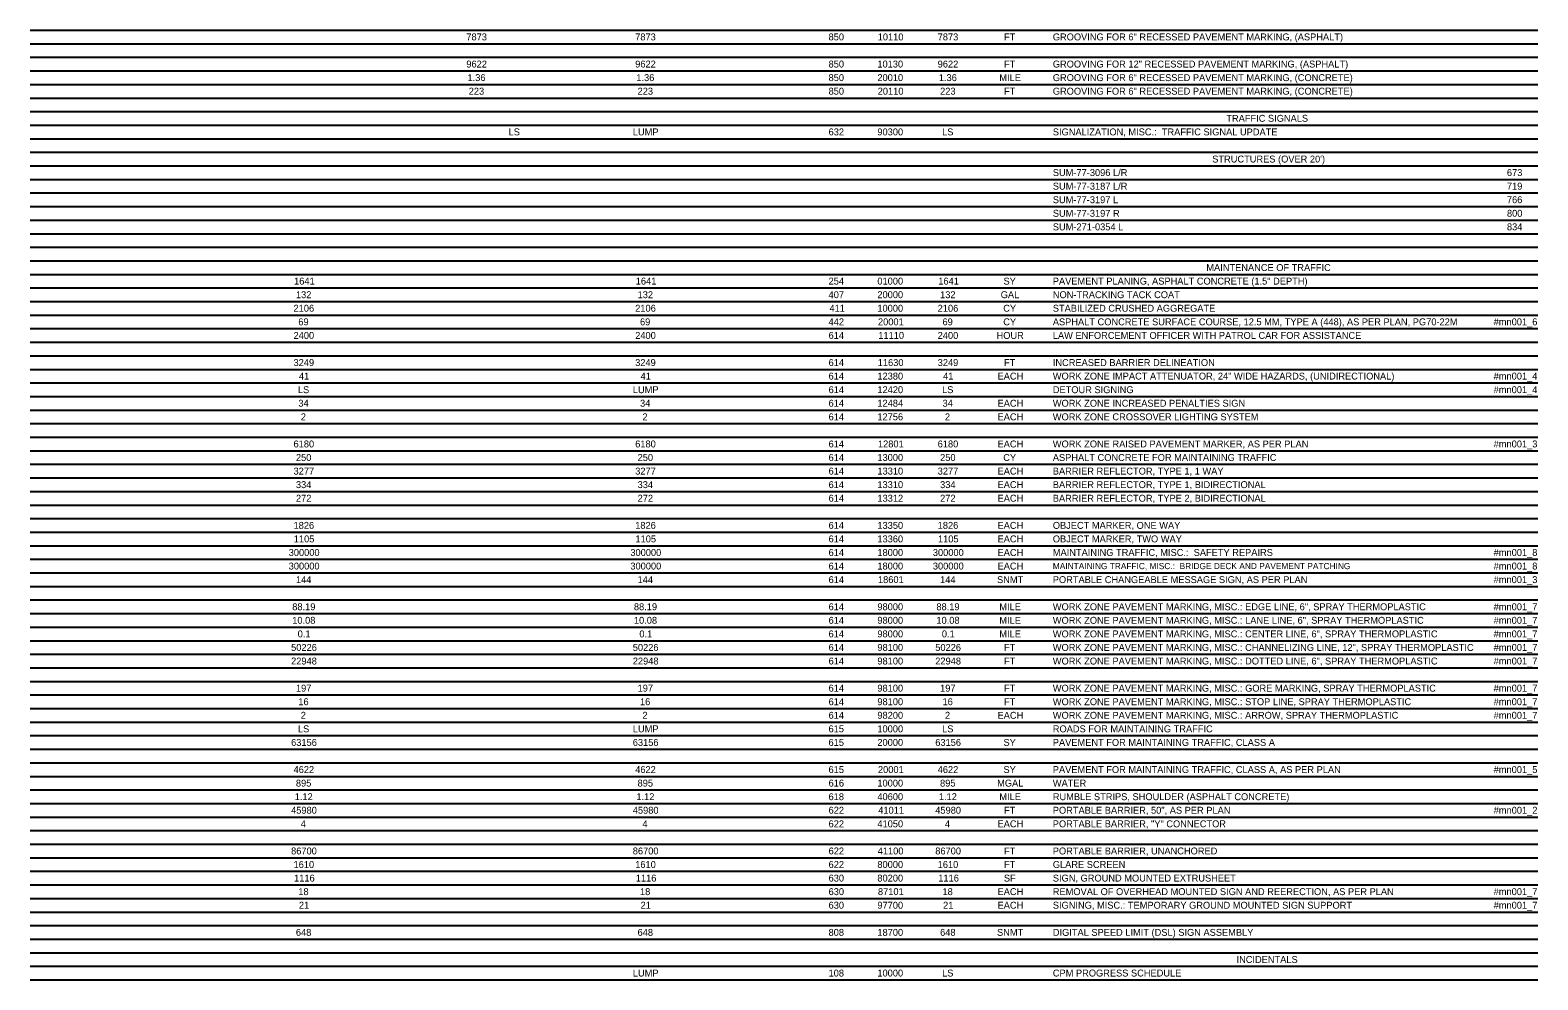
# Model space of a CAD drawing. Extents: x -542 to 295, y -281 to 32.
# Drawn here: x -364.38 to -333.88, y -153.25 to -134.04 of the extents above; entities that cross this region are included whole.
import ezdxf

# ---------------------------------------------------------------- set-up
doc = ezdxf.new("R2010")
doc.units = 0
doc.layers.add('SH_Data', color=7, linetype='Continuous')
doc.layers.add('SH_Text', color=7, linetype='Continuous')

msp = doc.modelspace()

# ---------------------------------------------------------------- linework, layer by layer
at = {"layer": 'SH_Data'}
for p, q in [((-364.38, -134.035), (-333.88, -134.035)), ((-364.38, -134.31), (-333.88, -134.31)), ((-364.38, -134.584), (-333.88, -134.584)), ((-364.38, -134.859), (-333.88, -134.859)), ((-364.38, -135.133), (-333.88, -135.133)), ((-364.38, -135.408), (-333.88, -135.408)), ((-364.38, -135.682), (-333.88, -135.682)), ((-364.38, -135.957), (-333.88, -135.957)), ((-364.38, -136.231), (-333.88, -136.231)), ((-364.38, -136.506), (-333.88, -136.506)), ((-364.38, -136.78), (-333.88, -136.78)), ((-364.38, -137.055), (-333.88, -137.055)), ((-364.38, -137.329), (-333.88, -137.329)), ((-364.38, -137.604), (-333.88, -137.604)), ((-364.38, -137.878), (-333.88, -137.878)), ((-364.38, -138.153), (-333.88, -138.153)), ((-364.38, -138.427), (-333.88, -138.427)), ((-364.38, -138.702), (-333.88, -138.702)), ((-364.38, -138.976), (-333.88, -138.976)), ((-364.38, -139.251), (-333.88, -139.251)), ((-364.38, -139.525), (-333.88, -139.525)), ((-364.38, -139.8), (-333.88, -139.8)), ((-364.38, -140.074), (-333.88, -140.074)), ((-364.38, -140.349), (-333.88, -140.349)), ((-364.38, -140.623), (-333.88, -140.623)), ((-364.38, -140.898), (-333.88, -140.898)), ((-364.38, -141.172), (-333.88, -141.172)), ((-364.38, -141.447), (-333.88, -141.447)), ((-364.38, -141.721), (-333.88, -141.721)), ((-364.38, -141.996), (-333.88, -141.996)), ((-364.38, -142.27), (-333.88, -142.27)), ((-364.38, -142.545), (-333.88, -142.545)), ((-364.38, -142.819), (-333.88, -142.819)), ((-364.38, -143.094), (-333.88, -143.094)), ((-364.38, -143.368), (-333.88, -143.368)), ((-364.38, -143.643), (-333.88, -143.643)), ((-364.38, -143.917), (-333.88, -143.917)), ((-364.38, -144.192), (-333.88, -144.192)), ((-364.38, -144.466), (-333.88, -144.466)), ((-364.38, -144.741), (-333.88, -144.741)), ((-364.38, -145.015), (-333.88, -145.015)), ((-364.38, -145.29), (-333.88, -145.29)), ((-364.38, -145.564), (-333.88, -145.564)), ((-364.38, -145.839), (-333.88, -145.839)), ((-364.38, -146.113), (-333.88, -146.113)), ((-364.38, -146.388), (-333.88, -146.388)), ((-364.38, -146.663), (-333.88, -146.663)), ((-364.38, -146.937), (-333.88, -146.937)), ((-364.38, -147.212), (-333.88, -147.212)), ((-364.38, -147.486), (-333.88, -147.486)), ((-364.38, -147.761), (-333.88, -147.761)), ((-364.38, -148.035), (-333.88, -148.035)), ((-364.38, -148.31), (-333.88, -148.31)), ((-364.38, -148.584), (-333.88, -148.584)), ((-364.38, -148.859), (-333.88, -148.859)), ((-364.38, -149.133), (-333.88, -149.133)), ((-364.38, -149.408), (-333.88, -149.408)), ((-364.38, -149.682), (-333.88, -149.682)), ((-364.38, -149.957), (-333.88, -149.957)), ((-364.38, -150.231), (-333.88, -150.231)), ((-364.38, -150.506), (-333.88, -150.506)), ((-364.38, -150.78), (-333.88, -150.78)), ((-364.38, -151.055), (-333.88, -151.055)), ((-364.38, -151.329), (-333.88, -151.329)), ((-364.38, -151.604), (-333.88, -151.604)), ((-364.38, -151.878), (-333.88, -151.878)), ((-364.38, -152.153), (-333.88, -152.153)), ((-364.38, -152.427), (-333.88, -152.427)), ((-364.38, -152.702), (-333.88, -152.702)), ((-364.38, -152.976), (-333.88, -152.976)), ((-364.38, -153.251), (-333.88, -153.251))]:
    msp.add_line(p, q, dxfattribs=at)

# ---------------------------------------------------------------- texts
at = {"layer": 'SH_Text'}
for s, height, p in [('7873', 0.14, (-355.556, -134.242)), ('7873', 0.14, (-352.14, -134.242)), ('850', 0.14, (-348.228, -134.242)), ('10110', 0.14, (-347.234, -134.242)), ('7873', 0.14, (-346.021, -134.242)), ('FT', 0.14, (-344.679, -134.242)), ('GROOVING FOR 6" RECESSED PAVEMENT MARKING, (ASPHALT)', 0.14, (-343.692, -134.242)), ('9622', 0.14, (-355.556, -134.791)), ('9622', 0.14, (-352.14, -134.791)), ('850', 0.14, (-348.228, -134.791)), ('10130', 0.14, (-347.241, -134.791)), ('9622', 0.14, (-346.021, -134.791)), ('FT', 0.14, (-344.679, -134.791)), ('GROOVING FOR 12" RECESSED PAVEMENT MARKING, (ASPHALT)', 0.14, (-343.692, -134.791)), ('1.36', 0.14, (-355.533, -135.066)), ('1.36', 0.14, (-352.117, -135.066)), ('850', 0.14, (-348.228, -135.066)), ('20010', 0.14, (-347.241, -135.066)), ('1.36', 0.14, (-345.998, -135.066)), ('MILE', 0.14, (-344.774, -135.066)), ('GROOVING FOR 6" RECESSED PAVEMENT MARKING, (CONCRETE)', 0.14, (-343.692, -135.066)), ('223', 0.14, (-355.508, -135.34)), ('223', 0.14, (-352.092, -135.34)), ('850', 0.14, (-348.228, -135.34)), ('20110', 0.14, (-347.234, -135.34)), ('223', 0.14, (-345.972, -135.34)), ('FT', 0.14, (-344.679, -135.34)), ('GROOVING FOR 6" RECESSED PAVEMENT MARKING, (CONCRETE)', 0.14, (-343.692, -135.34)), ('LS', 0.14, (-354.701, -136.164)), ('LUMP', 0.14, (-352.188, -136.164)), ('632', 0.14, (-348.228, -136.164)), ('90300', 0.14, (-347.241, -136.164)), ('LS', 0.14, (-345.932, -136.164)), ('SIGNALIZATION, MISC.:  TRAFFIC SIGNAL UPDATE', 0.14, (-343.692, -136.164)), ('TRAFFIC SIGNALS', 0.14, (-340.182, -135.889)), ("STRUCTURES (OVER 20')", 0.14, (-340.467, -136.713)), ('SUM-77-3096 L/R', 0.14, (-343.692, -136.987)), ('673', 0.14, (-334.506, -136.987)), ('SUM-77-3187 L/R', 0.14, (-343.692, -137.262)), ('719', 0.14, (-334.506, -137.262)), ('SUM-77-3197 L', 0.14, (-343.692, -137.536)), ('766', 0.14, (-334.506, -137.536)), ('SUM-77-3197 R', 0.14, (-343.692, -137.811)), ('800', 0.14, (-334.505, -137.811)), ('SUM-271-0354 L', 0.14, (-343.692, -138.085)), ('834', 0.14, (-334.505, -138.085)), ('MAINTENANCE OF TRAFFIC', 0.14, (-340.586, -138.909)), ('1641', 0.14, (-359.041, -139.183)), ('1641', 0.14, (-352.129, -139.183)), ('254', 0.14, (-348.228, -139.183)), ('01000', 0.14, (-347.241, -139.183)), ('1641', 0.14, (-346.009, -139.183)), ('SY', 0.14, (-344.69, -139.183)), ('PAVEMENT PLANING, ASPHALT CONCRETE (1.5" DEPTH)', 0.14, (-343.692, -139.183)), ('132', 0.14, (-359.003, -139.458)), ('132', 0.14, (-352.091, -139.458)), ('407', 0.14, (-348.228, -139.458)), ('20000', 0.14, (-347.241, -139.458)), ('132', 0.14, (-345.972, -139.458)), ('GAL', 0.14, (-344.746, -139.458)), ('NON-TRACKING TACK COAT', 0.14, (-343.692, -139.458)), ('2106', 0.14, (-359.052, -139.732)), ('2106', 0.14, (-352.14, -139.732)), ('411', 0.14, (-348.21, -139.732)), ('10000', 0.14, (-347.241, -139.732)), ('2106', 0.14, (-346.021, -139.732)), ('CY', 0.14, (-344.695, -139.732)), ('STABILIZED CRUSHED AGGREGATE', 0.14, (-343.692, -139.732)), ('69', 0.14, (-358.955, -140.007)), ('69', 0.14, (-352.043, -140.007)), ('442', 0.14, (-348.228, -140.007)), ('20001', 0.14, (-347.229, -140.007)), ('69', 0.14, (-345.924, -140.007)), ('CY', 0.14, (-344.695, -140.007)), ('ASPHALT CONCRETE SURFACE COURSE, 12.5 MM, TYPE A (448), AS PER PLAN, PG70-22M', 0.14, (-343.692, -140.007)), ('#mn001_6', 0.14, (-334.774, -140.007)), ('2400', 0.14, (-359.052, -140.282)), ('2400', 0.14, (-352.14, -140.282)), ('614', 0.14, (-348.228, -140.282)), ('11110', 0.14, (-347.222, -140.282)), ('2400', 0.14, (-346.021, -140.282)), ('HOUR', 0.14, (-344.83, -140.282)), ('LAW ENFORCEMENT OFFICER WITH PATROL CAR FOR ASSISTANCE', 0.14, (-343.692, -140.282)), ('3249', 0.14, (-359.052, -140.831)), ('3249', 0.14, (-352.141, -140.831)), ('614', 0.14, (-348.228, -140.831)), ('11630', 0.14, (-347.234, -140.831)), ('3249', 0.14, (-346.021, -140.831)), ('FT', 0.14, (-344.679, -140.831)), ('INCREASED BARRIER DELINEATION', 0.14, (-343.692, -140.831)), ('41', 0.14, (-358.943, -141.105)), ('41', 0.14, (-352.031, -141.105)), ('614', 0.14, (-348.228, -141.105)), ('12380', 0.14, (-347.241, -141.105)), ('41', 0.14, (-345.912, -141.105)), ('EACH', 0.14, (-344.81, -141.105)), ('WORK ZONE IMPACT ATTENUATOR, 24" WIDE HAZARDS, (UNIDIRECTIONAL)', 0.14, (-343.692, -141.105)), ('#mn001_4', 0.14, (-334.774, -141.105)), ('LS', 0.14, (-358.963, -141.38)), ('34', 0.14, (-358.954, -141.654)), ('LUMP', 0.14, (-352.188, -141.38)), ('34', 0.14, (-352.042, -141.654)), ('614', 0.14, (-348.228, -141.38)), ('614', 0.14, (-348.228, -141.654)), ('12420', 0.14, (-347.241, -141.38)), ('12484', 0.14, (-347.241, -141.654)), ('LS', 0.14, (-345.932, -141.38)), ('34', 0.14, (-345.923, -141.654)), ('EACH', 0.14, (-344.81, -141.654)), ('WORK ZONE INCREASED PENALTIES SIGN', 0.14, (-343.692, -141.654)), ('DETOUR SIGNING', 0.14, (-343.692, -141.38)), ('#mn001_4', 0.14, (-334.774, -141.38)), ('2', 0.14, (-358.905, -141.929)), ('2', 0.14, (-351.993, -141.929)), ('614', 0.14, (-348.228, -141.929)), ('12756', 0.14, (-347.241, -141.929)), ('2', 0.14, (-345.874, -141.929)), ('EACH', 0.14, (-344.81, -141.929)), ('WORK ZONE CROSSOVER LIGHTING SYSTEM', 0.14, (-343.692, -141.929)), ('6180', 0.14, (-359.052, -142.478)), ('6180', 0.14, (-352.14, -142.478)), ('614', 0.14, (-348.228, -142.478)), ('12801', 0.14, (-347.229, -142.478)), ('6180', 0.14, (-346.021, -142.478)), ('EACH', 0.14, (-344.81, -142.478)), ('WORK ZONE RAISED PAVEMENT MARKER, AS PER PLAN', 0.14, (-343.692, -142.478)), ('#mn001_3', 0.14, (-334.774, -142.478)), ('250', 0.14, (-359.003, -142.752)), ('250', 0.14, (-352.091, -142.752)), ('614', 0.14, (-348.228, -142.752)), ('13000', 0.14, (-347.241, -142.752)), ('250', 0.14, (-345.972, -142.752)), ('CY', 0.14, (-344.695, -142.752)), ('ASPHALT CONCRETE FOR MAINTAINING TRAFFIC', 0.14, (-343.692, -142.752)), ('3277', 0.14, (-359.052, -143.027)), ('3277', 0.14, (-352.14, -143.027)), ('614', 0.14, (-348.228, -143.027)), ('13310', 0.14, (-347.241, -143.027)), ('3277', 0.14, (-346.021, -143.027)), ('EACH', 0.14, (-344.81, -143.027)), ('BARRIER REFLECTOR, TYPE 1, 1 WAY', 0.14, (-343.692, -143.027)), ('334', 0.14, (-359.003, -143.301)), ('334', 0.14, (-352.091, -143.301)), ('614', 0.14, (-348.228, -143.301)), ('13310', 0.14, (-347.241, -143.301)), ('334', 0.14, (-345.972, -143.301)), ('EACH', 0.14, (-344.81, -143.301)), ('BARRIER REFLECTOR, TYPE 1, BIDIRECTIONAL', 0.14, (-343.692, -143.301)), ('272', 0.14, (-359.003, -143.576)), ('272', 0.14, (-352.091, -143.576)), ('614', 0.14, (-348.228, -143.576)), ('13312', 0.14, (-347.24, -143.576)), ('272', 0.14, (-345.972, -143.576)), ('EACH', 0.14, (-344.81, -143.576)), ('BARRIER REFLECTOR, TYPE 2, BIDIRECTIONAL', 0.14, (-343.692, -143.576)), ('1826', 0.14, (-359.052, -144.125)), ('1105', 0.14, (-359.047, -144.399)), ('1826', 0.14, (-352.14, -144.125)), ('1105', 0.14, (-352.135, -144.399)), ('614', 0.14, (-348.228, -144.125)), ('614', 0.14, (-348.228, -144.399)), ('13350', 0.14, (-347.241, -144.125)), ('13360', 0.14, (-347.241, -144.399)), ('1826', 0.14, (-346.021, -144.125)), ('1105', 0.14, (-346.015, -144.399)), ('EACH', 0.14, (-344.81, -144.125)), ('EACH', 0.14, (-344.81, -144.399)), ('OBJECT MARKER, ONE WAY', 0.14, (-343.692, -144.125)), ('OBJECT MARKER, TWO WAY', 0.14, (-343.692, -144.399)), ('300000', 0.14, (-359.15, -144.674)), ('300000', 0.14, (-352.238, -144.674)), ('614', 0.14, (-348.228, -144.674)), ('18000', 0.14, (-347.241, -144.674)), ('300000', 0.14, (-346.119, -144.674)), ('EACH', 0.14, (-344.81, -144.674)), ('MAINTAINING TRAFFIC, MISC.:  SAFETY REPAIRS', 0.14, (-343.692, -144.674)), ('#mn001_8', 0.14, (-334.774, -144.674)), ('300000', 0.14, (-359.15, -144.948)), ('300000', 0.14, (-352.238, -144.948)), ('614', 0.14, (-348.228, -144.948)), ('18000', 0.14, (-347.241, -144.948)), ('300000', 0.14, (-346.119, -144.948)), ('EACH', 0.14, (-344.81, -144.948)), ('MAINTAINING TRAFFIC, MISC.:  BRIDGE DECK AND PAVEMENT PATCHING', 0.126, (-343.692, -144.941)), ('#mn001_8', 0.14, (-334.774, -144.948)), ('144', 0.14, (-359.003, -145.223)), ('144', 0.14, (-352.091, -145.223)), ('614', 0.14, (-348.228, -145.223)), ('18601', 0.14, (-347.229, -145.223)), ('144', 0.14, (-345.972, -145.223)), ('SNMT', 0.14, (-344.82, -145.223)), ('PORTABLE CHANGEABLE MESSAGE SIGN, AS PER PLAN', 0.14, (-343.692, -145.223)), ('#mn001_3', 0.14, (-334.774, -145.223)), ('88.19', 0.14, (-359.078, -145.772)), ('88.19', 0.14, (-352.166, -145.772)), ('614', 0.14, (-348.228, -145.772)), ('98000', 0.14, (-347.241, -145.772)), ('88.19', 0.14, (-346.047, -145.772)), ('MILE', 0.14, (-344.774, -145.772)), ('WORK ZONE PAVEMENT MARKING, MISC.: EDGE LINE, 6", SPRAY THERMOPLASTIC', 0.14, (-343.692, -145.772)), ('#mn001_7', 0.14, (-334.774, -145.772)), ('10.08', 0.14, (-359.078, -146.046)), ('10.08', 0.14, (-352.166, -146.046)), ('614', 0.14, (-348.228, -146.046)), ('98000', 0.14, (-347.241, -146.046)), ('10.08', 0.14, (-346.047, -146.046)), ('MILE', 0.14, (-344.774, -146.046)), ('WORK ZONE PAVEMENT MARKING, MISC.: LANE LINE, 6", SPRAY THERMOPLASTIC', 0.14, (-343.692, -146.046)), ('#mn001_7', 0.14, (-334.774, -146.046)), ('0.1', 0.14, (-358.968, -146.321)), ('0.1', 0.14, (-352.056, -146.321)), ('614', 0.14, (-348.228, -146.321)), ('98000', 0.14, (-347.241, -146.321)), ('0.1', 0.14, (-345.937, -146.321)), ('MILE', 0.14, (-344.774, -146.321)), ('WORK ZONE PAVEMENT MARKING, MISC.: CENTER LINE, 6", SPRAY THERMOPLASTIC', 0.14, (-343.692, -146.321)), ('#mn001_7', 0.14, (-334.774, -146.321)), ('50226', 0.14, (-359.101, -146.595)), ('50226', 0.14, (-352.189, -146.595)), ('614', 0.14, (-348.228, -146.595)), ('98100', 0.14, (-347.241, -146.595)), ('50226', 0.14, (-346.07, -146.595)), ('FT', 0.14, (-344.679, -146.595)), ('WORK ZONE PAVEMENT MARKING, MISC.: CHANNELIZING LINE, 12", SPRAY THERMOPLASTIC', 0.14, (-343.692, -146.595)), ('#mn001_7', 0.14, (-334.774, -146.595)), ('22948', 0.14, (-359.101, -146.87)), ('22948', 0.14, (-352.189, -146.87)), ('614', 0.14, (-348.228, -146.87)), ('98100', 0.14, (-347.241, -146.87)), ('22948', 0.14, (-346.07, -146.87)), ('FT', 0.14, (-344.679, -146.87)), ('WORK ZONE PAVEMENT MARKING, MISC.: DOTTED LINE, 6", SPRAY THERMOPLASTIC', 0.14, (-343.692, -146.87)), ('#mn001_7', 0.14, (-334.774, -146.87)), ('197', 0.14, (-359.003, -147.419)), ('197', 0.14, (-352.092, -147.419)), ('614', 0.14, (-348.228, -147.419)), ('98100', 0.14, (-347.241, -147.419)), ('197', 0.14, (-345.972, -147.419)), ('FT', 0.14, (-344.679, -147.419)), ('WORK ZONE PAVEMENT MARKING, MISC.: GORE MARKING, SPRAY THERMOPLASTIC', 0.14, (-343.692, -147.419)), ('#mn001_7', 0.14, (-334.774, -147.419)), ('16', 0.14, (-358.955, -147.693)), ('16', 0.14, (-352.043, -147.693)), ('614', 0.14, (-348.228, -147.693)), ('98100', 0.14, (-347.241, -147.693)), ('16', 0.14, (-345.923, -147.693)), ('FT', 0.14, (-344.679, -147.693)), ('WORK ZONE PAVEMENT MARKING, MISC.: STOP LINE, SPRAY THERMOPLASTIC', 0.14, (-343.692, -147.693)), ('#mn001_7', 0.14, (-334.774, -147.693)), ('2', 0.14, (-358.905, -147.968)), ('2', 0.14, (-351.993, -147.968)), ('614', 0.14, (-348.228, -147.968)), ('98200', 0.14, (-347.241, -147.968)), ('2', 0.14, (-345.874, -147.968)), ('EACH', 0.14, (-344.81, -147.968)), ('WORK ZONE PAVEMENT MARKING, MISC.: ARROW, SPRAY THERMOPLASTIC', 0.14, (-343.692, -147.968)), ('#mn001_7', 0.14, (-334.774, -147.968)), ('LS', 0.14, (-358.963, -148.242)), ('LUMP', 0.14, (-352.188, -148.242)), ('615', 0.14, (-348.229, -148.242)), ('10000', 0.14, (-347.241, -148.242)), ('LS', 0.14, (-345.932, -148.242)), ('ROADS FOR MAINTAINING TRAFFIC', 0.14, (-343.692, -148.242)), ('63156', 0.14, (-359.101, -148.517)), ('63156', 0.14, (-352.189, -148.517)), ('615', 0.14, (-348.229, -148.517)), ('20000', 0.14, (-347.241, -148.517)), ('63156', 0.14, (-346.07, -148.517)), ('SY', 0.14, (-344.69, -148.517)), ('PAVEMENT FOR MAINTAINING TRAFFIC, CLASS A', 0.14, (-343.692, -148.517)), ('4622', 0.14, (-359.052, -149.066)), ('4622', 0.14, (-352.14, -149.066)), ('615', 0.14, (-348.229, -149.066)), ('20001', 0.14, (-347.229, -149.066)), ('4622', 0.14, (-346.021, -149.066)), ('SY', 0.14, (-344.69, -149.066)), ('PAVEMENT FOR MAINTAINING TRAFFIC, CLASS A, AS PER PLAN', 0.14, (-343.692, -149.066)), ('#mn001_5', 0.14, (-334.774, -149.066)), ('895', 0.14, (-359.004, -149.34)), ('895', 0.14, (-352.092, -149.34)), ('616', 0.14, (-348.228, -149.34)), ('10000', 0.14, (-347.241, -149.34)), ('895', 0.14, (-345.973, -149.34)), ('MGAL', 0.14, (-344.818, -149.34)), ('WATER', 0.14, (-343.692, -149.34)), ('45980', 0.14, (-359.101, -149.889)), ('1.12', 0.14, (-359.028, -149.615)), ('45980', 0.14, (-352.189, -149.889)), ('1.12', 0.14, (-352.116, -149.615)), ('618', 0.14, (-348.229, -149.615)), ('622', 0.14, (-348.228, -149.889)), ('40600', 0.14, (-347.241, -149.615)), ('41011', 0.14, (-347.223, -149.889)), ('45980', 0.14, (-346.07, -149.889)), ('1.12', 0.14, (-345.997, -149.615)), ('MILE', 0.14, (-344.774, -149.615)), ('FT', 0.14, (-344.679, -149.889)), ('RUMBLE STRIPS, SHOULDER (ASPHALT CONCRETE)', 0.14, (-343.692, -149.615)), ('PORTABLE BARRIER, 50", AS PER PLAN', 0.14, (-343.692, -149.889)), ('#mn001_2', 0.14, (-334.773, -149.889)), ('4', 0.14, (-358.905, -150.164)), ('4', 0.14, (-351.993, -150.164)), ('622', 0.14, (-348.228, -150.164)), ('41050', 0.14, (-347.241, -150.164)), ('4', 0.14, (-345.874, -150.164)), ('EACH', 0.14, (-344.81, -150.164)), ('PORTABLE BARRIER, "Y" CONNECTOR', 0.14, (-343.692, -150.164)), ('86700', 0.14, (-359.101, -150.713)), ('86700', 0.14, (-352.189, -150.713)), ('622', 0.14, (-348.228, -150.713)), ('41100', 0.14, (-347.234, -150.713)), ('86700', 0.14, (-346.07, -150.713)), ('FT', 0.14, (-344.679, -150.713)), ('PORTABLE BARRIER, UNANCHORED', 0.14, (-343.692, -150.713)), ('1610', 0.14, (-359.052, -150.987)), ('1610', 0.14, (-352.14, -150.987)), ('622', 0.14, (-348.228, -150.987)), ('80000', 0.14, (-347.241, -150.987)), ('1610', 0.14, (-346.021, -150.987)), ('FT', 0.14, (-344.679, -150.987)), ('GLARE SCREEN', 0.14, (-343.692, -150.987)), ('1116', 0.14, (-359.04, -151.262)), ('1116', 0.14, (-352.128, -151.262)), ('630', 0.14, (-348.228, -151.262)), ('80200', 0.14, (-347.241, -151.262)), ('1116', 0.14, (-346.009, -151.262)), ('SF', 0.14, (-344.682, -151.262)), ('SIGN, GROUND MOUNTED EXTRUSHEET', 0.14, (-343.692, -151.262)), ('18', 0.14, (-358.955, -151.536)), ('18', 0.14, (-352.043, -151.536)), ('630', 0.14, (-348.228, -151.536)), ('87101', 0.14, (-347.229, -151.536)), ('18', 0.14, (-345.924, -151.536)), ('EACH', 0.14, (-344.81, -151.536)), ('REMOVAL OF OVERHEAD MOUNTED SIGN AND REERECTION, AS PER PLAN', 0.14, (-343.692, -151.536)), ('#mn001_7', 0.14, (-334.774, -151.536)), ('21', 0.14, (-358.943, -151.811)), ('21', 0.14, (-352.031, -151.811)), ('630', 0.14, (-348.228, -151.811)), ('97700', 0.14, (-347.241, -151.811)), ('21', 0.14, (-345.912, -151.811)), ('EACH', 0.14, (-344.81, -151.811)), ('SIGNING, MISC.: TEMPORARY GROUND MOUNTED SIGN SUPPORT', 0.14, (-343.692, -151.811)), ('#mn001_7', 0.14, (-334.774, -151.811)), ('648', 0.14, (-359.004, -152.36)), ('648', 0.14, (-352.092, -152.36)), ('808', 0.14, (-348.229, -152.36)), ('18700', 0.14, (-347.241, -152.36)), ('648', 0.14, (-345.972, -152.36)), ('SNMT', 0.14, (-344.82, -152.36)), ('DIGITAL SPEED LIMIT (DSL) SIGN ASSEMBLY', 0.14, (-343.692, -152.36)), ('INCIDENTALS', 0.14, (-339.976, -152.909)), ('LUMP', 0.14, (-352.188, -153.183)), ('108', 0.14, (-348.229, -153.183)), ('10000', 0.14, (-347.241, -153.183)), ('LS', 0.14, (-345.932, -153.183)), ('CPM PROGRESS SCHEDULE', 0.14, (-343.692, -153.183))]:
    msp.add_text(s, height=height, dxfattribs=at).set_placement(p)

doc.saveas('drawing.dxf')
